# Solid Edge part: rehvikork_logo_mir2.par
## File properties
Author: KULL
Template: Iso Metric Part.par
Last saved by: KULL
Revision: 2
Application: Solid Edge
Accuracy: 0,990
Username: KULL
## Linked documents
rehvikork_logo.par
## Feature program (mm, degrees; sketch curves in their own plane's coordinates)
part copy "CopiedPart_1"
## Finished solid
Body 1: solid body, 86 faces, 199 edges, 116 vertices, 2 separate solids.
  Faces by surface: spline 40, blend 36, sphere 8, cone 1, torus 1
  Edges by curve: intersection 112, line 32, circle 29, curve on surface 26
Bounding box of the edges (mm; curved faces can reach further): 1.405 x 13.917 x 13.917, from (-0.4589, -6.9587, -6.9587) to (0.946, 6.9587, 6.9587).
Conical faces (half-angle, radius in mm at the cone's reference point): 11.8765 deg R7 x1
Toroidal faces (ring radius, tube radius in mm): R6.763 r0.2 x1
Spherical faces by radius (mm): R0.2 x4, R33.3132 x2, R34.0132 x2
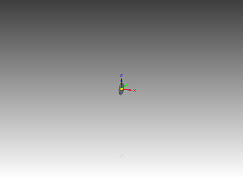
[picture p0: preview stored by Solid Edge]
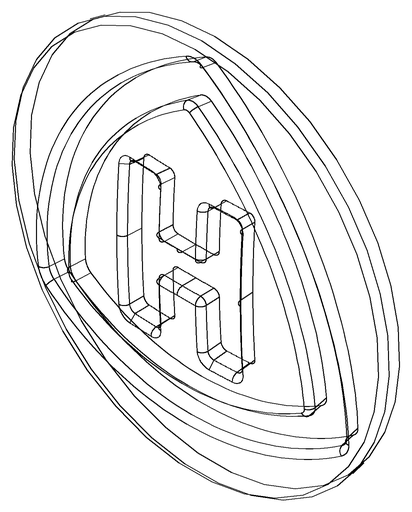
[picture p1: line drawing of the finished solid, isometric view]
